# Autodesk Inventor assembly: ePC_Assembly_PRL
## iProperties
Shininess: 64.0
Length Units: 11272
Angle Units: 11279
Time Units: 11290
Mass Units: 11286
Length Display Precision: 3
Angle Display Precision: 2
Compacted: True
Part Number: ePC_Assembly_PRL
Document SubType Name: Assembly
Created: 2004-08
Designer: John Blackburn
Manufacturer: Standard
Standards Organization: Custom
Density: 0.0
Volumn: 0.0
Area: 0.0
PropertySet Name: Model Information
Control State: 0
Master: False
Checked Out: False
Author: John Blackburn
